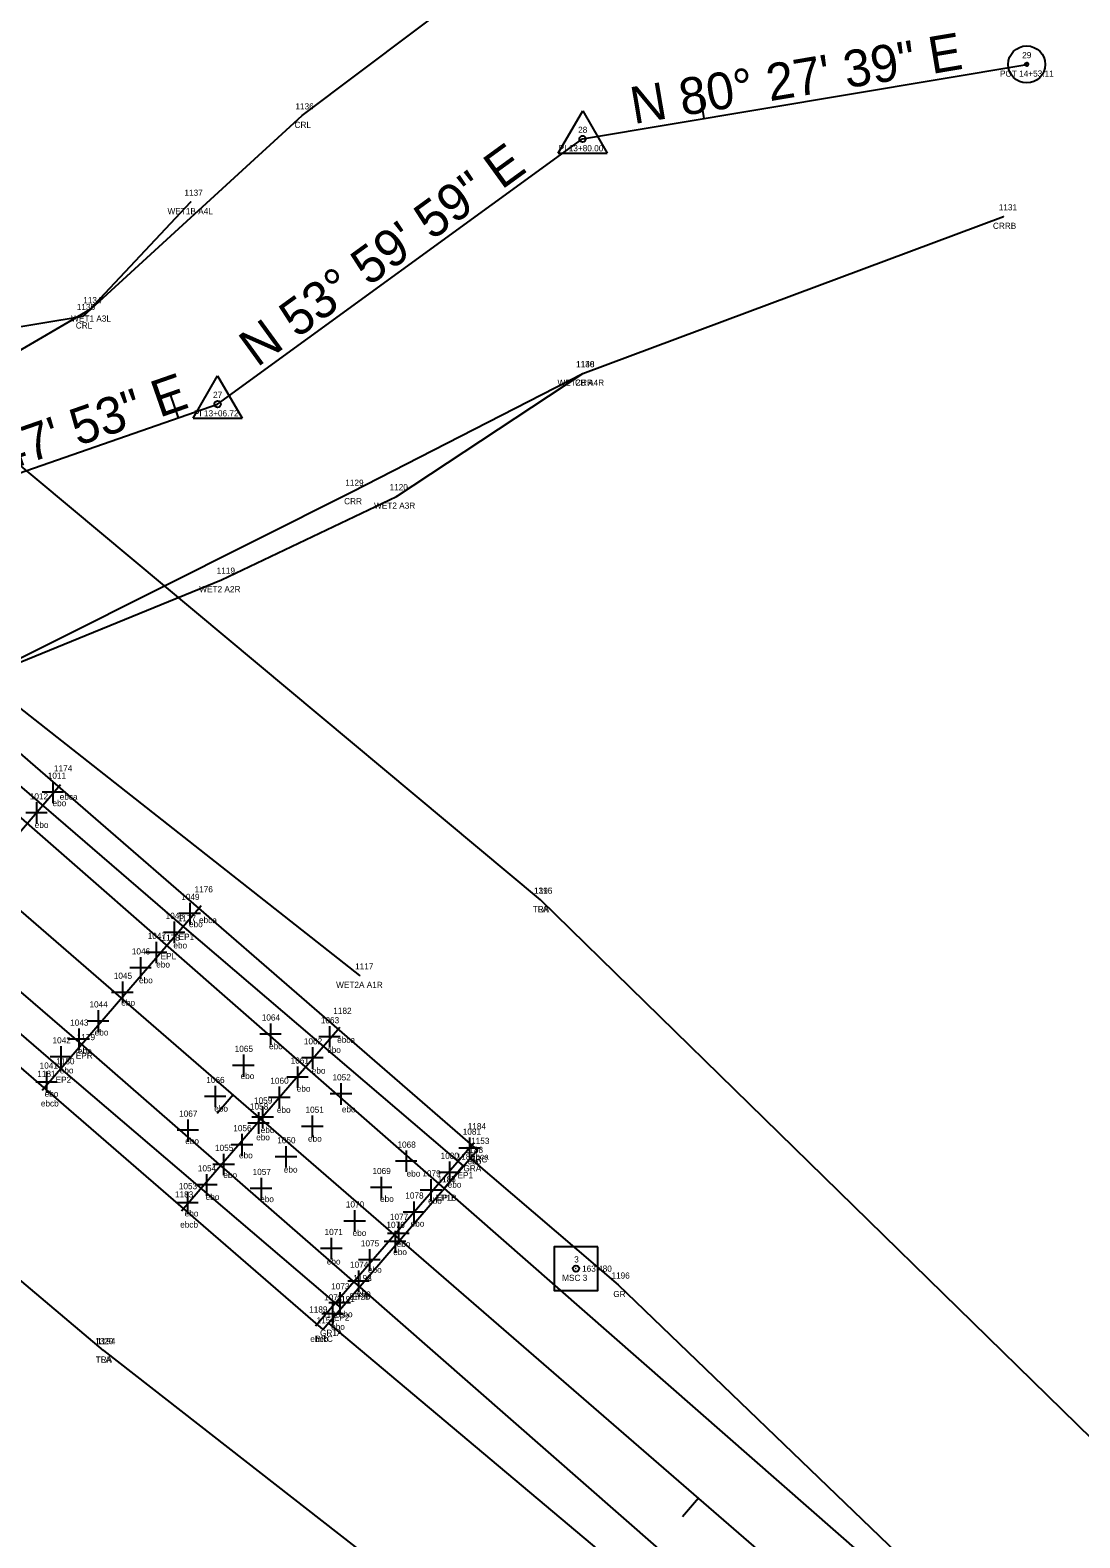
# Model space of a CAD drawing. Extents: x 2085293 to 2087464, y 876528 to 879458.
# Drawn here: x 2086486.4 to 2086656.8, y 878364.4 to 878609.3 of the extents above; entities that cross this region are included whole.
import ezdxf

# ---------------------------------------------------------------- set-up
doc = ezdxf.new("R2010")
doc.units = 0
for name, color, linetype in [('RD_EX_Bridge', 7, 'Continuous'), ('RD_EX_Bridge_txCode', 7, 'Continuous'), ('RD_EX_GuardRail', 7, 'Continuous'), ('RD_EX_GuardRail_txCode', 7, 'Continuous'), ('RD_EX_H2O', 7, 'Continuous'), ('RD_EX_H2O_txCode', 7, 'Continuous'), ('RD_EX_H2O_WetLd', 7, 'Continuous'), ('RD_EX_H2O_WetLd_txCode', 7, 'Continuous'), ('RD_EX_Misc', 7, 'Continuous'), ('RD_EX_Misc_txCode', 7, 'Continuous'), ('RD_EX_Road', 7, 'Continuous'), ('RD_EX_Road_txCode', 7, 'Continuous'), ('RD_EX_VEG', 7, 'Continuous'), ('RD_EX_VEG_txCode', 7, 'Continuous'), ('RD_HC_Cl', 7, 'Continuous'), ('RD_HC_Data', 7, 'Continuous'), ('RD_HC_Data_Tic', 7, 'Continuous'), ('RD_HC_Survey', 7, 'Continuous'), ('RD_HC_txCode', 7, 'Continuous'), ('RD_SMD_Locator', 7, 'Continuous')]:
    doc.layers.add(name, color=color, linetype=linetype)

msp = doc.modelspace()

# ---------------------------------------------------------------- linework, layer by layer
at = {"layer": 'RD_EX_Bridge'}
msp.add_lwpolyline([(2086377.74, 878584.61), (2086559.01, 878427.4), (2086533.93, 878398.26), (2086352.47, 878555.51), (2086377.74, 878584.61)], dxfattribs=at)
at = {"layer": 'RD_EX_GuardRail'}
for points in [[(2086557.97, 878425.94), (2086581.82, 878405.53), (2086628.55, 878360.61), (2086786.69, 878222.41)], [(2086534.85, 878399.22), (2086608.85, 878337.02), (2086682.81, 878273.24), (2086766.26, 878201.43), (2086929.1, 878059.13), (2086996.85, 877995.24), (2087038.82, 877951.38), (2087074.29, 877911.24), (2087106.23, 877872.89), (2087136.47, 877833.47), (2087169.27, 877786), (2087201.97, 877733.76), (2087231.51, 877680.63), (2087254.1, 877635.42)]]:
    msp.add_lwpolyline(points, dxfattribs=at)
at = {"layer": 'RD_EX_H2O'}
for points in [[(2086350.1, 878485.82), (2086392.62, 878510.5), (2086406.71, 878533.27), (2086442.18, 878554.15), (2086494.98, 878562.84), (2086530.51, 878595.43), (2086576.04, 878629.72), (2086651.92, 878628.48)], [(2086371.86, 878446.8), (2086433.83, 878478.04), (2086460.24, 878487.42), (2086475.2, 878502.52), (2086538.58, 878534.3), (2086576.08, 878553.56), (2086644.41, 878579.03)]]:
    msp.add_lwpolyline(points, dxfattribs=at)
at = {"layer": 'RD_EX_H2O_WetLd'}
for points in [[(2086428.59, 878541.31), (2086482.9, 878556.26), (2086496.03, 878563.96), (2086512.46, 878581.4)], [(2086539.89, 878455.74), (2086478.45, 878504.11), (2086517.42, 878520.02), (2086545.81, 878533.58), (2086576.08, 878553.56)]]:
    msp.add_lwpolyline(points, dxfattribs=at)
at = {"layer": 'RD_EX_Misc'}
for p, q in [((2086491.28, 878486.71), (2086465.7, 878456.82)), ((2086490.03, 878487.27), (2086490.03, 878483.77)), ((2086491.78, 878485.52), (2086488.28, 878485.52)), ((2086489.14, 878482.16), (2086485.64, 878482.16)), ((2086487.39, 878483.91), (2086487.39, 878480.41)), ((2086514.14, 878467.06), (2086488.29, 878437.09)), ((2086512.26, 878467.58), (2086512.26, 878464.08)), ((2086514.01, 878465.83), (2086510.51, 878465.83)), ((2086511.49, 878462.76), (2086507.99, 878462.76)), ((2086509.74, 878464.51), (2086509.74, 878461.01)), ((2086506.82, 878461.25), (2086506.82, 878457.75)), ((2086504.27, 878458.73), (2086504.27, 878455.23)), ((2086508.57, 878459.5), (2086505.07, 878459.5)), ((2086501.32, 878454.77), (2086501.32, 878451.27)), ((2086506.02, 878456.98), (2086502.52, 878456.98)), ((2086503.07, 878453.02), (2086499.57, 878453.02)), ((2086497.37, 878450.12), (2086497.37, 878446.62)), ((2086499.12, 878448.37), (2086495.62, 878448.37)), ((2086525.37, 878447.99), (2086525.37, 878444.49)), ((2086534.96, 878447.55), (2086534.96, 878444.05)), ((2086495.98, 878445.41), (2086492.48, 878445.41)), ((2086494.23, 878447.16), (2086494.23, 878443.66)), ((2086536.63, 878447.33), (2086510.93, 878417.51)), ((2086527.12, 878446.24), (2086523.62, 878446.24)), ((2086536.71, 878445.8), (2086533.21, 878445.8)), ((2086493.11, 878442.54), (2086489.61, 878442.54)), ((2086491.36, 878444.29), (2086491.36, 878440.79)), ((2086520.97, 878442.91), (2086520.97, 878439.41)), ((2086532.2, 878444.12), (2086532.2, 878440.62)), ((2086489, 878440.18), (2086489, 878436.68)), ((2086522.72, 878441.16), (2086519.22, 878441.16)), ((2086529.77, 878441), (2086529.77, 878437.5)), ((2086533.95, 878442.37), (2086530.45, 878442.37)), ((2086490.75, 878438.43), (2086487.25, 878438.43)), ((2086516.39, 878437.85), (2086516.39, 878434.35)), ((2086526.8, 878437.72), (2086526.8, 878434.22)), ((2086531.52, 878439.25), (2086528.02, 878439.25)), ((2086536.82, 878438.27), (2086536.82, 878434.77)), ((2086518.14, 878436.1), (2086514.64, 878436.1)), ((2086528.55, 878435.97), (2086525.05, 878435.97)), ((2086538.57, 878436.52), (2086535.07, 878436.52)), ((2086525.84, 878432.76), (2086522.34, 878432.76)), ((2086523.43, 878433.54), (2086523.43, 878430.04)), ((2086524.09, 878434.51), (2086524.09, 878431.01)), ((2086532.16, 878433.01), (2086532.16, 878429.51)), ((2086513.7, 878430.63), (2086510.2, 878430.63)), ((2086511.95, 878432.38), (2086511.95, 878428.88)), ((2086525.18, 878431.79), (2086521.68, 878431.79)), ((2086533.91, 878431.26), (2086530.41, 878431.26)), ((2086522.49, 878428.27), (2086518.99, 878428.27)), ((2086520.74, 878430.02), (2086520.74, 878426.52)), ((2086527.89, 878428.05), (2086527.89, 878424.55)), ((2086558.46, 878428.58), (2086532.71, 878398.82)), ((2086557.7, 878429.44), (2086557.7, 878425.94)), ((2086517.76, 878426.81), (2086517.76, 878423.31)), ((2086529.64, 878426.3), (2086526.14, 878426.3)), ((2086549.15, 878425.6), (2086545.65, 878425.6)), ((2086547.4, 878427.35), (2086547.4, 878423.85)), ((2086554.42, 878425.53), (2086554.42, 878422.03)), ((2086559.45, 878427.69), (2086555.95, 878427.69)), ((2086514.96, 878423.5), (2086514.96, 878420)), ((2086519.51, 878425.06), (2086516.01, 878425.06)), ((2086543.34, 878423.06), (2086543.34, 878419.56)), ((2086556.17, 878423.78), (2086552.67, 878423.78)), ((2086511.88, 878420.6), (2086511.88, 878417.1)), ((2086516.71, 878421.75), (2086513.21, 878421.75)), ((2086525.6, 878421.16), (2086522.1, 878421.16)), ((2086523.85, 878422.91), (2086523.85, 878419.41)), ((2086545.09, 878421.31), (2086541.59, 878421.31)), ((2086553.17, 878420.92), (2086549.67, 878420.92)), ((2086551.42, 878422.67), (2086551.42, 878419.17)), ((2086513.63, 878418.85), (2086510.13, 878418.85)), ((2086548.65, 878419.08), (2086548.65, 878415.58)), ((2086540.78, 878415.88), (2086537.28, 878415.88)), ((2086539.03, 878417.63), (2086539.03, 878414.13)), ((2086546.15, 878415.62), (2086546.15, 878412.12)), ((2086550.4, 878417.33), (2086546.9, 878417.33)), ((2086535.25, 878413.16), (2086535.25, 878409.66)), ((2086547.9, 878413.87), (2086544.4, 878413.87)), ((2086545.61, 878414.31), (2086545.61, 878410.81)), ((2086537, 878411.41), (2086533.5, 878411.41)), ((2086541.44, 878411.31), (2086541.44, 878407.81)), ((2086547.36, 878412.56), (2086543.86, 878412.56)), ((2086543.19, 878409.56), (2086539.69, 878409.56)), ((2086541.42, 878406.1), (2086537.92, 878406.1)), ((2086539.67, 878407.85), (2086539.67, 878404.35)), ((2086536.62, 878404.33), (2086536.62, 878400.83)), ((2086538.37, 878402.58), (2086534.87, 878402.58)), ((2086535.47, 878402.54), (2086535.47, 878399.04)), ((2086537.22, 878400.79), (2086533.72, 878400.79))]:
    msp.add_line(p, q, dxfattribs=at)
at = {"layer": 'RD_EX_Road'}
for points in [[(2086372.48, 878578.63), (2086375.14, 878581.18), (2086443.25, 878522.25), (2086511.37, 878463.55), (2086556.66, 878424.84), (2086553.57, 878421.17)], [(2086372.48, 878578.63), (2086440.93, 878519.74), (2086508.75, 878460.4), (2086553.57, 878421.17), (2086626.32, 878357.37), (2086700.27, 878293.03), (2086782.28, 878221.68)], [(2086358.19, 878561.82), (2086355.45, 878558.6), (2086422.99, 878499.64), (2086491.68, 878440.33), (2086536.87, 878401.71), (2086539.89, 878405.13)], [(2086358.19, 878561.82), (2086426.45, 878503.36), (2086494.99, 878444.26), (2086539.89, 878405.13), (2086612.82, 878341.2), (2086686.27, 878277.41), (2086769.9, 878205.27), (2086844.45, 878140.34), (2086932.82, 878063.42), (2086964.75, 878034.46), (2087001.42, 877999.16), (2087042.78, 877955.43), (2087078.39, 877914.63), (2087110.34, 877876.43), (2087140.35, 877836.91), (2087173.38, 877789.29), (2087206.69, 877736.44), (2087236.08, 877683.18), (2087259.17, 877638.22), (2087287.12, 877578.12)]]:
    msp.add_lwpolyline(points, dxfattribs=at)
at = {"layer": 'RD_EX_VEG'}
for points in [[(2086498.28, 878394.88), (2086329.73, 878537.22), (2086212.13, 878664.14), (2086102.42, 878763.92), (2085939.19, 878906.04), (2085793.62, 879021.84)], [(2086569.24, 878468.04), (2086400.81, 878608.73), (2086323.2, 878689.41), (2086335.21, 878726.99)], [(2086569.24, 878468.04), (2086721.69, 878318.95), (2086888.62, 878178.86), (2086990.44, 878072.84), (2086995.6, 878081.01), (2086998.55, 878096.25)], [(2086498.28, 878394.88), (2086673.32, 878258.25), (2086834.35, 878132.96), (2086951.61, 878021.81), (2086985.65, 877983.51), (2087068.57, 877904.56), (2087196.19, 877730.31), (2087248.69, 877630.56), (2087313.65, 877471.66), (2087371.52, 877270.9)]]:
    msp.add_lwpolyline(points, dxfattribs=at)
at = {"layer": 'RD_HC_Cl'}
for p, q in [((2086923.31, 878086.15), (2085624.78, 879211.84)), ((2086576.06, 878591.63), (2086648.16, 878603.75)), ((2086516.79, 878548.57), (2086576.06, 878591.63)), ((2086458.69, 878528.33), (2086516.79, 878548.57))]:
    msp.add_line(p, q, dxfattribs=at)
at = {"layer": 'RD_HC_Data'}
for p, q in [((2086572.09, 878589.34), (2086576.07, 878596.22)), ((2086576.07, 878596.22), (2086580.03, 878589.34)), ((2086572.09, 878589.34), (2086580.03, 878589.34)), ((2086512.81, 878546.27), (2086516.79, 878553.15)), ((2086516.79, 878553.15), (2086520.76, 878546.27)), ((2086512.81, 878546.27), (2086520.76, 878546.27))]:
    msp.add_line(p, q, dxfattribs=at)
for centre, radius in [((2086648.16, 878603.75), 3), ((2086648.16, 878603.75), 0.282), ((2086576.06, 878591.63), 0.529), ((2086516.79, 878548.57), 0.529)]:
    msp.add_circle(centre, radius, dxfattribs=at)
at = {"layer": 'RD_HC_Data_Tic'}
for p, q in [((2086595.79, 878594.95), (2086595.13, 878598.89)), ((2086510.43, 878546.35), (2086509.12, 878550.13)), ((2086519.32, 878436.36), (2086516.7, 878433.34)), ((2086594.88, 878370.86), (2086592.26, 878367.84))]:
    msp.add_line(p, q, dxfattribs=at)
at = {"layer": 'RD_HC_Survey'}
msp.add_lwpolyline([(2086578.51, 878411.69), (2086571.43, 878411.69), (2086571.43, 878404.62), (2086578.51, 878404.62)], close=True, dxfattribs=at)
msp.add_circle((2086574.97, 878408.15), 0.5, dxfattribs=at)
at = {"layer": 'RD_SMD_Locator'}
for centre in [(2086648.16, 878603.75), (2086530.51, 878595.43), (2086576.06, 878591.63), (2086512.46, 878581.4), (2086644.41, 878579.03), (2086494.98, 878562.84), (2086496.03, 878563.96), (2086576.08, 878553.56), (2086576.08, 878553.56), (2086516.79, 878548.57), (2086538.58, 878534.3), (2086545.81, 878533.58), (2086517.42, 878520.02), (2086569.24, 878468.04), (2086569.24, 878468.04), (2086511.37, 878463.55), (2086508.75, 878460.4), (2086539.89, 878455.74), (2086494.99, 878444.26), (2086491.68, 878440.33), (2086557.97, 878425.94), (2086559.01, 878427.4), (2086556.66, 878424.84), (2086553.57, 878421.17), (2086553.57, 878421.17), (2086574.97, 878408.15), (2086539.89, 878405.13), (2086539.89, 878405.13), (2086581.82, 878405.53), (2086536.87, 878401.71), (2086534.85, 878399.22), (2086533.93, 878398.26), (2086498.28, 878394.88), (2086498.28, 878394.88)]:
    msp.add_circle(centre, 0.001, dxfattribs=at)

# ---------------------------------------------------------------- texts
at = {"layer": 'RD_EX_Bridge_txCode'}
for s, p in [('1153', (2086557.95, 878428.4)), ('BRC', (2086557.76, 878425.4)), ('1154', (2086532.87, 878399.26)), ('BRC', (2086532.68, 878396.26))]:
    msp.add_text(s, height=1, dxfattribs=at).set_placement(p)
at = {"layer": 'RD_EX_GuardRail_txCode'}
for s, p in [('1188', (2086556.91, 878426.94)), ('GRA', (2086556.7, 878423.94)), ('1196', (2086580.74, 878406.53)), ('GR', (2086581.04, 878403.53)), ('1190', (2086533.75, 878400.22)), ('GR1A', (2086533.42, 878397.22))]:
    msp.add_text(s, height=1, dxfattribs=at).set_placement(p)
at = {"layer": 'RD_EX_H2O_txCode'}
for s, p in [('1136', (2086529.42, 878596.43)), ('CRL', (2086529.28, 878593.43)), ('1131', (2086643.63, 878580.03)), ('CRRB', (2086642.68, 878577.03)), ('1135', (2086493.92, 878563.84)), ('CRL', (2086493.76, 878560.84)), ('1130', (2086574.98, 878554.56)), ('CRR', (2086574.83, 878551.56)), ('1129', (2086537.52, 878535.3)), ('CRR', (2086537.33, 878532.3))]:
    msp.add_text(s, height=1, dxfattribs=at).set_placement(p)
at = {"layer": 'RD_EX_H2O_WetLd_txCode'}
for s, p in [('1137', (2086511.4, 878582.4)), ('WET1B A4L', (2086508.66, 878579.4)), ('1134', (2086494.97, 878564.96)), ('WET1 A3L', (2086493.01, 878561.96)), ('1148', (2086575.02, 878554.56)), ('WET2B A4R', (2086571.97, 878551.56)), ('1120', (2086544.71, 878534.58)), ('WET2 A3R', (2086542.19, 878531.58)), ('1119', (2086516.64, 878521.02)), ('WET2 A2R', (2086513.81, 878518.02)), ('1117', (2086539.11, 878456.74)), ('WET2A A1R', (2086536.03, 878453.74))]:
    msp.add_text(s, height=1, dxfattribs=at).set_placement(p)
at = {"layer": 'RD_EX_Misc_txCode'}
for s, p in [('1174', (2086490.22, 878488.91)), ('1011', (2086489.21, 878487.72)), ('1012', (2086486.29, 878484.36)), ('ebo', (2086489.98, 878483.26)), ('ebca', (2086491.15, 878484.3)), ('ebo', (2086487.1, 878479.72)), ('1176', (2086513.05, 878469.26)), ('1049', (2086510.88, 878468.03)), ('1048', (2086508.35, 878464.96)), ('ebo', (2086512.14, 878463.61)), ('ebca', (2086513.77, 878464.27)), ('1047', (2086505.44, 878461.7)), ('1046', (2086502.86, 878459.18)), ('ebo', (2086509.61, 878460.16)), ('ebo', (2086506.82, 878457.06)), ('1045', (2086499.93, 878455.22)), ('ebo', (2086504.03, 878454.49)), ('1044', (2086495.98, 878450.57)), ('ebo', (2086501.15, 878450.86)), ('1182', (2086535.57, 878449.53)), ('1043', (2086492.85, 878447.61)), ('1064', (2086523.96, 878448.44)), ('1063', (2086533.55, 878448)), ('1042', (2086489.98, 878444.74)), ('ebo', (2086496.83, 878446.02)), ('1062', (2086530.79, 878444.57)), ('ebca', (2086536.2, 878444.83)), ('ebo', (2086494.12, 878443)), ('1065', (2086519.56, 878443.36)), ('ebo', (2086525.14, 878443.79)), ('ebo', (2086534.57, 878443.18)), ('1181', (2086487.51, 878439.29)), ('1041', (2086487.89, 878440.63)), ('ebo', (2086491.16, 878439.86)), ('1061', (2086528.65, 878441.45)), ('ebo', (2086532.08, 878439.82)), ('1066', (2086514.95, 878438.3)), ('ebo', (2086520.52, 878438.94)), ('1060', (2086525.35, 878438.17)), ('ebo', (2086529.64, 878436.89)), ('1052', (2086535.44, 878438.72)), ('ebcb', (2086488.09, 878434.49)), ('ebo', (2086488.71, 878436.06)), ('1059', (2086522.7, 878434.96)), ('1067', (2086510.54, 878432.83)), ('ebo', (2086516.24, 878433.66)), ('1058', (2086522.04, 878433.99)), ('ebo', (2086526.41, 878433.44)), ('1051', (2086531.06, 878433.46)), ('ebo', (2086536.96, 878433.53)), ('1056', (2086519.33, 878430.47)), ('ebo', (2086523.79, 878430.17)), ('1081', (2086556.59, 878429.89)), ('1184', (2086557.4, 878430.78)), ('ebo', (2086511.53, 878428.38)), ('1055', (2086516.37, 878427.26)), ('ebo', (2086523.05, 878428.99)), ('1050', (2086526.47, 878428.5)), ('ebo', (2086531.47, 878428.77)), ('1068', (2086545.99, 878427.8)), ('ebo', (2086520.26, 878426.06)), ('1080', (2086553, 878425.98)), ('ebo', (2086557.38, 878425.1)), ('ebca', (2086557.9, 878425.87)), ('1054', (2086513.58, 878423.95)), ('ebo', (2086517.72, 878422.88)), ('1057', (2086522.47, 878423.36)), ('ebo', (2086527.54, 878423.75)), ('1069', (2086541.93, 878423.51)), ('ebo', (2086547.48, 878423.1)), ('1079', (2086550.03, 878423.12)), ('1183', (2086509.87, 878419.71)), ('1053', (2086510.49, 878421.05)), ('1078', (2086547.26, 878419.53)), ('ebo', (2086554.15, 878421.31)), ('ebo', (2086514.85, 878419.3)), ('ebo', (2086523.7, 878418.95)), ('1070', (2086537.61, 878418.08)), ('ebo', (2086543.16, 878418.99)), ('ebo', (2086550.97, 878418.69)), ('ebcb', (2086510.71, 878414.81)), ('ebo', (2086511.44, 878416.63)), ('1076', (2086544.2, 878414.76)), ('1077', (2086544.76, 878416.07)), ('ebo', (2086548.13, 878414.98)), ('1071', (2086534.15, 878413.61)), ('ebo', (2086538.71, 878413.45)), ('1075', (2086540.05, 878411.76)), ('ebo', (2086545.3, 878410.35)), ('ebo', (2086545.86, 878411.66)), ('ebo', (2086534.52, 878408.82)), ('1074', (2086538.29, 878408.3)), ('ebo', (2086541.2, 878407.47)), ('1073', (2086535.23, 878404.78)), ('1072', (2086534.08, 878402.99)), ('ebo', (2086539.41, 878403.67)), ('1189', (2086531.65, 878401.02)), ('ebo', (2086536.48, 878400.26)), ('ebo', (2086535.22, 878398.21)), ('ebcb', (2086531.84, 878396.23))]:
    msp.add_text(s, height=1, dxfattribs=at).set_placement(p)
at = {"layer": 'RD_EX_Road_txCode'}
for s, p in [('1177', (2086510.31, 878464.55)), ('1178', (2086507.68, 878461.4)), ('EP1', (2086510.45, 878461.55)), ('EPL', (2086507.54, 878458.4)), ('1179', (2086493.92, 878445.26)), ('EPR', (2086493.76, 878442.26)), ('1180', (2086490.58, 878441.33)), ('EP2', (2086490.48, 878438.33)), ('1185', (2086555.6, 878425.84)), ('1186', (2086552.49, 878422.17)), ('1187', (2086552.51, 878422.17)), ('EP1', (2086555.74, 878422.84)), ('EP1B', (2086552.18, 878419.17)), ('EPL', (2086552.37, 878419.17)), ('163.480', (2086575.97, 878407.65)), ('1192', (2086538.83, 878406.13)), ('1193', (2086538.83, 878406.13)), ('1191', (2086536.09, 878402.71)), ('EP2B', (2086538.21, 878403.13)), ('EPR', (2086538.66, 878403.13)), ('EP2', (2086535.66, 878399.71))]:
    msp.add_text(s, height=1, dxfattribs=at).set_placement(p)
at = {"layer": 'RD_EX_VEG_txCode'}
for s, p in [('1316', (2086568.16, 878469.04)), ('1195', (2086568.18, 878469.04)), ('TRA', (2086567.96, 878466.04)), ('TLA', (2086567.98, 878466.04)), ('1320', (2086496.89, 878395.88)), ('1194', (2086497.22, 878395.88)), ('TRA', (2086496.99, 878392.88)), ('TLA', (2086497.02, 878392.88))]:
    msp.add_text(s, height=1, dxfattribs=at).set_placement(p)
at = {"layer": 'RD_HC_Data'}
for s, rotation, p in [('N 80%%d 27\' 39" E', 9.5392, (2086584.36, 878594.04)), ('N 53%%d 59\' 59" E', 36.0002, (2086523.2, 878554.46)), ('N 70%%d 47\' 53" E', 19.2019, (2086460.99, 878530.19))]:
    msp.add_text(s, height=6, rotation=rotation, dxfattribs=at).set_placement(p)
at = {"layer": 'RD_HC_txCode'}
for s, p in [('29', (2086647.43, 878604.75)), ('POT 14+53.11', (2086643.82, 878601.75)), ('28', (2086575.33, 878592.63)), ('PI 13+80.00', (2086572.17, 878589.63)), ('27', (2086516.05, 878549.57)), ('PI 13+06.72', (2086512.94, 878546.57)), ('3', (2086574.69, 878409.15)), ('MSC 3', (2086572.73, 878406.15))]:
    msp.add_text(s, height=1, dxfattribs=at).set_placement(p)

doc.saveas('drawing.dxf')
